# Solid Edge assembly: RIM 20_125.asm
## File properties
Title: Zylinder
Author: ahadarics
Template: iso metric assembly.asm
Last saved by: ahadarics
Revision: 11
Application: Solid Edge
Username: ahadarics
Dokumentum tartalom típus: 1
Document Number: RIM 20/125
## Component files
Kit_2.par
Profilrohr.par
Kolbenstange.par
Kit_1.par
Mutter_1.par
Mutter_2.par
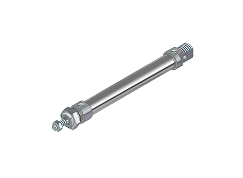
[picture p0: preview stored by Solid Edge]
